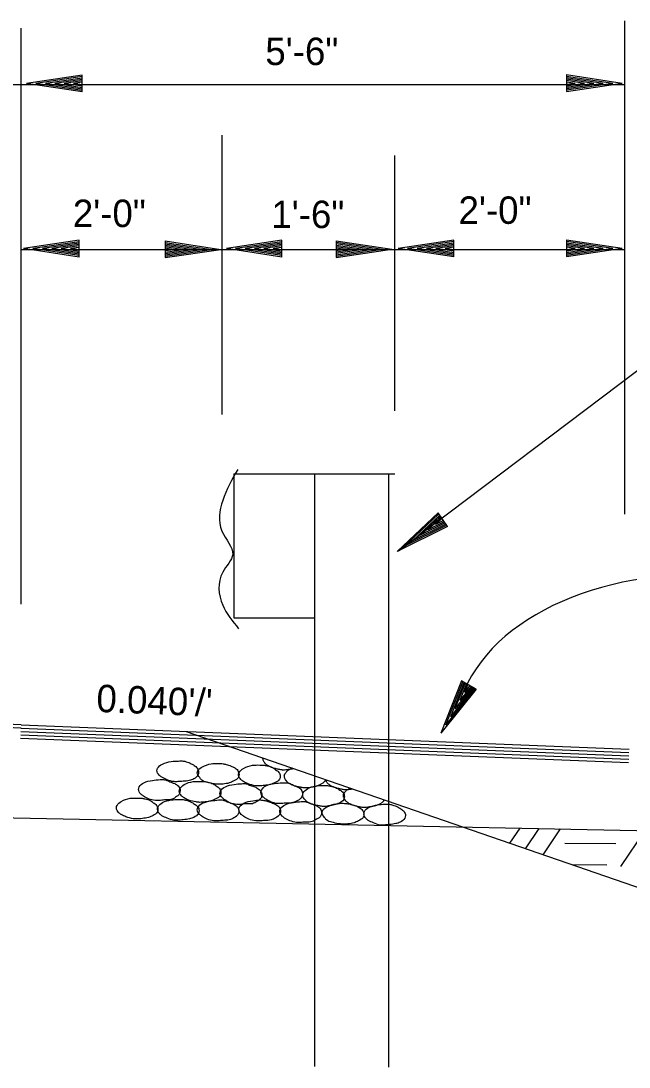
# Model space of a CAD drawing. Extents: x 1929624 to 1935547, y 596315 to 605721.
# Drawn here: x 1933028.1 to 1933162.8, y 604729.9 to 604961.5 of the extents above; entities that cross this region are included whole.
import ezdxf

# ---------------------------------------------------------------- set-up
doc = ezdxf.new("R2010")
doc.units = 0
doc.layers.add('Default', color=7, linetype='Continuous')
doc.layers.add('R_Border', color=7, linetype='Continuous')

msp = doc.modelspace()

# ---------------------------------------------------------------- linework, layer by layer
at = {"layer": 'Default'}
for p, q in [((1933161.84, 604852.3), (1933161.84, 604961.54)), ((1933028.14, 604832.41), (1933028.14, 604959.96)), ((1933148.9, 604949.65), (1933161.23, 604947.78)), ((1933148.9, 604949.65), (1933148.9, 604945.94)), ((1932831.31, 604947.46), (1933161.84, 604947.46)), ((1933041.68, 604949.53), (1933029.35, 604947.68)), ((1933041.68, 604945.81), (1933029.35, 604947.68)), ((1933041.68, 604949.21), (1933031.42, 604947.68)), ((1933041.68, 604946.13), (1933031.42, 604947.68)), ((1933041.68, 604948.89), (1933033.53, 604947.68)), ((1933041.68, 604946.45), (1933033.53, 604947.68)), ((1933041.68, 604948.59), (1933035.6, 604947.68)), ((1933041.68, 604946.75), (1933035.6, 604947.68)), ((1933041.68, 604948.27), (1933037.67, 604947.68)), ((1933041.68, 604947.07), (1933037.67, 604947.68)), ((1933041.68, 604947.95), (1933039.73, 604947.68)), ((1933041.68, 604947.39), (1933039.73, 604947.68)), ((1933041.68, 604945.81), (1933041.68, 604949.53)), ((1933148.9, 604949.33), (1933159.16, 604947.78)), ((1933148.9, 604949.01), (1933157.04, 604947.78)), ((1933148.9, 604948.72), (1933154.98, 604947.78)), ((1933148.9, 604948.4), (1933152.91, 604947.78)), ((1933148.9, 604948.08), (1933150.84, 604947.78)), ((1933148.9, 604945.94), (1933161.23, 604947.78)), ((1933148.9, 604947.19), (1933152.91, 604947.78)), ((1933148.9, 604946.58), (1933157.04, 604947.78)), ((1933148.9, 604946.26), (1933159.16, 604947.78)), ((1933148.9, 604946.87), (1933154.98, 604947.78)), ((1933148.9, 604947.51), (1933150.84, 604947.78)), ((1933072.7, 604874.4), (1933072.7, 604936.27)), ((1933110.91, 604875.2), (1933110.91, 604931.76)), ((1933041.01, 604912.97), (1933028.69, 604911.12)), ((1933041.01, 604912.65), (1933030.75, 604911.12)), ((1933041.01, 604909.25), (1933041.01, 604912.97)), ((1933060.03, 604912.84), (1933072.36, 604910.97)), ((1933060.03, 604912.84), (1933060.03, 604909.13)), ((1933060.03, 604912.52), (1933070.29, 604910.97)), ((1933085.91, 604912.97), (1933073.59, 604911.12)), ((1933085.91, 604912.65), (1933075.65, 604911.12)), ((1933085.91, 604909.25), (1933085.91, 604912.97)), ((1933097.9, 604912.87), (1933110.22, 604911)), ((1933097.9, 604912.87), (1933097.9, 604909.15)), ((1933097.9, 604912.55), (1933108.16, 604911)), ((1933124, 604912.99), (1933111.67, 604911.15)), ((1933124, 604912.67), (1933113.74, 604911.15)), ((1933124, 604909.28), (1933124, 604912.99)), ((1933148.9, 604913.07), (1933161.23, 604911.2)), ((1933148.9, 604913.07), (1933148.9, 604909.35)), ((1933148.9, 604912.75), (1933159.16, 604911.2)), ((1933028.14, 604910.9), (1933161.84, 604910.9)), ((1933041.01, 604909.25), (1933028.69, 604911.12)), ((1933041.01, 604909.57), (1933030.75, 604911.12)), ((1933041.01, 604912.33), (1933032.87, 604911.12)), ((1933041.01, 604909.89), (1933032.87, 604911.12)), ((1933041.01, 604912.03), (1933034.93, 604911.12)), ((1933041.01, 604910.19), (1933034.93, 604911.12)), ((1933041.01, 604911.71), (1933037, 604911.12)), ((1933041.01, 604910.51), (1933037, 604911.12)), ((1933041.01, 604911.39), (1933039.07, 604911.12)), ((1933041.01, 604910.83), (1933039.07, 604911.12)), ((1933060.03, 604912.2), (1933068.17, 604910.97)), ((1933060.03, 604911.91), (1933066.11, 604910.97)), ((1933060.03, 604911.59), (1933064.04, 604910.97)), ((1933060.03, 604911.27), (1933061.97, 604910.97)), ((1933060.03, 604909.13), (1933072.36, 604910.97)), ((1933060.03, 604910.38), (1933064.04, 604910.97)), ((1933060.03, 604909.77), (1933068.17, 604910.97)), ((1933060.03, 604909.45), (1933070.29, 604910.97)), ((1933060.03, 604910.06), (1933066.11, 604910.97)), ((1933060.03, 604910.7), (1933061.97, 604910.97)), ((1933085.91, 604909.25), (1933073.59, 604911.12)), ((1933085.91, 604909.57), (1933075.65, 604911.12)), ((1933085.91, 604912.33), (1933077.77, 604911.12)), ((1933085.91, 604909.89), (1933077.77, 604911.12)), ((1933085.91, 604912.03), (1933079.84, 604911.12)), ((1933085.91, 604910.19), (1933079.84, 604911.12)), ((1933085.91, 604911.71), (1933081.9, 604911.12)), ((1933085.91, 604910.51), (1933081.9, 604911.12)), ((1933085.91, 604911.39), (1933083.97, 604911.12)), ((1933085.91, 604910.83), (1933083.97, 604911.12)), ((1933097.9, 604912.23), (1933106.04, 604911)), ((1933097.9, 604911.93), (1933103.97, 604911)), ((1933097.9, 604911.61), (1933101.91, 604911)), ((1933097.9, 604911.29), (1933099.84, 604911)), ((1933097.9, 604909.15), (1933110.22, 604911)), ((1933097.9, 604910.41), (1933101.91, 604911)), ((1933097.9, 604909.79), (1933106.04, 604911)), ((1933097.9, 604909.47), (1933108.16, 604911)), ((1933097.9, 604910.09), (1933103.97, 604911)), ((1933097.9, 604910.73), (1933099.84, 604911)), ((1933124, 604909.28), (1933111.67, 604911.15)), ((1933124, 604909.6), (1933113.74, 604911.15)), ((1933124, 604912.35), (1933115.86, 604911.15)), ((1933124, 604909.92), (1933115.86, 604911.15)), ((1933124, 604912.06), (1933117.92, 604911.15)), ((1933124, 604910.21), (1933117.92, 604911.15)), ((1933124, 604911.74), (1933119.99, 604911.15)), ((1933124, 604910.53), (1933119.99, 604911.15)), ((1933124, 604911.42), (1933122.06, 604911.15)), ((1933124, 604910.85), (1933122.06, 604911.15)), ((1933148.9, 604912.43), (1933157.04, 604911.2)), ((1933148.9, 604912.13), (1933154.98, 604911.2)), ((1933148.9, 604911.81), (1933152.91, 604911.2)), ((1933148.9, 604911.49), (1933150.84, 604911.2)), ((1933148.9, 604909.35), (1933161.23, 604911.2)), ((1933148.9, 604910.61), (1933152.91, 604911.2)), ((1933148.9, 604909.99), (1933157.04, 604911.2)), ((1933148.9, 604909.67), (1933159.16, 604911.2)), ((1933148.9, 604910.29), (1933154.98, 604911.2)), ((1933148.9, 604910.92), (1933150.84, 604911.2)), ((1933111.72, 604844.22), (1933181.03, 604896.61)), ((1933075.26, 604861.23), (1933075.26, 604829.39)), ((1933075.26, 604861.23), (1933110.91, 604861.23)), ((1933093.1, 604861.23), (1933093.1, 604730.04)), ((1933109.48, 604861.08), (1933109.48, 604729.92)), ((1933120.47, 604852.64), (1933111.4, 604844.08)), ((1933120.66, 604852.4), (1933113.08, 604845.24)), ((1933122.56, 604849.64), (1933120.47, 604852.64)), ((1933120.86, 604852.11), (1933114.88, 604846.51)), ((1933122.19, 604850.14), (1933114.88, 604846.51)), ((1933120.98, 604851.85), (1933116.55, 604847.67)), ((1933122.02, 604850.4), (1933116.55, 604847.67)), ((1933121.17, 604851.64), (1933118.22, 604848.85)), ((1933121.82, 604850.67), (1933118.22, 604848.85)), ((1933121.34, 604851.37), (1933119.92, 604850.04)), ((1933121.7, 604850.95), (1933119.92, 604850.04)), ((1933122.56, 604849.64), (1933111.4, 604844.08)), ((1933122.41, 604849.87), (1933113.08, 604845.24)), ((1933075.26, 604829.39), (1933093.1, 604829.39)), ((1933125.7, 604815.46), (1933121.12, 604803.85)), ((1933125.94, 604815.27), (1933122.16, 604805.65)), ((1933128.9, 604813.59), (1933125.7, 604815.46)), ((1933128.9, 604813.59), (1933121.12, 604803.85)), ((1933128.65, 604813.76), (1933122.16, 604805.65)), ((1933126.24, 604815.12), (1933123.21, 604807.49)), ((1933128.33, 604813.89), (1933123.21, 604807.49)), ((1933126.49, 604814.97), (1933124.22, 604809.24)), ((1933128.08, 604814.06), (1933124.22, 604809.24)), ((1933126.78, 604814.82), (1933125.28, 604811.06)), ((1933127.81, 604814.21), (1933125.28, 604811.06)), ((1933127.08, 604814.65), (1933126.34, 604812.83)), ((1933127.54, 604814.38), (1933126.34, 604812.83)), ((1933028.14, 604805.69), (1932880.52, 604811.6)), ((1933028.14, 604804.96), (1932880.52, 604810.86)), ((1933028.08, 604804.22), (1933162.73, 604798.83)), ((1933028.1, 604804.96), (1933162.76, 604799.57)), ((1933028.14, 604805.69), (1933162.8, 604800.31)), ((1933064.67, 604804.23), (1933125.91, 604783.09)), ((1933028.02, 604802.74), (1933162.68, 604797.35)), ((1933028.05, 604803.48), (1933162.7, 604798.09)), ((1932826.87, 604789.04), (1933220.25, 604781.21)), ((1933125.91, 604783.09), (1933249.97, 604740.26))]:
    msp.add_line(p, q, dxfattribs=at)
msp.add_ellipse((1933185.01, 604798.43), major_axis=(-60.8, 7.42), ratio=0.655798, start_param=4.712389, end_param=6.093533, dxfattribs=at)
for points in [[(1933076.12, 604862.26), (1933072.78, 604855.35), (1933072.6, 604848.6), (1933075.01, 604843.41), (1933072.78, 604839.48), (1933072.78, 604832.22), (1933076.32, 604826.98)], [(1933063.01, 604797.68), (1933061.38, 604797.58), (1933059.42, 604796.99), (1933058.38, 604796.06), (1933058.23, 604795.52), (1933058.73, 604794.53), (1933059.32, 604794.09), (1933060.45, 604793.55), (1933062.02, 604793.11), (1933062.86, 604793.11), (1933064.04, 604793.2), (1933065.37, 604793.35), (1933066.4, 604793.75), (1933067.29, 604794.58), (1933067.44, 604795.22), (1933067.14, 604796.11), (1933066.5, 604796.7), (1933065.81, 604797.09), (1933064.73, 604797.53), (1933064.04, 604797.68), (1933063.01, 604797.68)], [(1933071.82, 604797.16), (1933070.2, 604797.06), (1933068.28, 604796.37), (1933067.3, 604795.58), (1933067.15, 604795.04), (1933067.69, 604794.01), (1933068.13, 604793.47), (1933069.31, 604792.97), (1933070.79, 604792.63), (1933071.63, 604792.53), (1933072.86, 604792.58), (1933074.24, 604792.83), (1933075.22, 604793.27), (1933076.25, 604794.06), (1933076.4, 604794.7), (1933076.11, 604795.58), (1933075.37, 604796.22), (1933074.63, 604796.57), (1933073.55, 604796.91), (1933072.86, 604797.06), (1933071.82, 604797.16)], [(1933081, 604796.79), (1933079.38, 604796.74), (1933077.41, 604796.05), (1933076.43, 604795.16), (1933076.28, 604794.57), (1933076.82, 604793.59), (1933077.36, 604793.15), (1933078.44, 604792.65), (1933080.02, 604792.21), (1933080.85, 604792.16), (1933082.03, 604792.26), (1933083.36, 604792.51), (1933084.4, 604792.9), (1933085.38, 604793.69), (1933085.53, 604794.28), (1933085.23, 604795.16), (1933084.5, 604795.75), (1933083.81, 604796.25), (1933082.72, 604796.59), (1933082.03, 604796.74), (1933081, 604796.79)], [(1933081.62, 604798.38), (1933081.62, 604798.35), (1933081.62, 604798.28), (1933081.63, 604798.21), (1933081.7, 604797.95), (1933081.82, 604797.68), (1933081.97, 604797.43), (1933082.07, 604797.3), (1933082.17, 604797.18), (1933082.42, 604796.93), (1933082.71, 604796.74), (1933082.97, 604796.59), (1933083.24, 604796.46), (1933083.51, 604796.35), (1933083.79, 604796.25), (1933084.57, 604796.03), (1933085.36, 604795.85), (1933085.78, 604795.78), (1933085.99, 604795.76), (1933086.2, 604795.75), (1933086.79, 604795.78), (1933087.09, 604795.81), (1933087.38, 604795.85), (1933087.9, 604795.93), (1933088.42, 604796.03)], [(1933088.28, 604796.08), (1933087.98, 604795.96), (1933087.74, 604795.85), (1933087.5, 604795.73), (1933087.21, 604795.55), (1933086.95, 604795.33), (1933086.73, 604795.08), (1933086.62, 604794.94), (1933086.51, 604794.79), (1933086.44, 604794.66), (1933086.39, 604794.52), (1933086.36, 604794.39), (1933086.36, 604794.32), (1933086.37, 604794.25), (1933086.44, 604793.98), (1933086.56, 604793.72), (1933086.71, 604793.47), (1933086.81, 604793.34), (1933086.91, 604793.22), (1933087.16, 604792.97), (1933087.45, 604792.78), (1933087.71, 604792.63), (1933087.98, 604792.5), (1933088.25, 604792.38), (1933088.53, 604792.28), (1933089.31, 604792.06), (1933090.11, 604791.89), (1933090.94, 604791.79), (1933091.09, 604791.79), (1933091.24, 604791.8), (1933091.53, 604791.82), (1933092.12, 604791.89), (1933092.46, 604791.94), (1933092.79, 604792), (1933093.12, 604792.06), (1933093.45, 604792.14), (1933093.72, 604792.21), (1933093.98, 604792.3), (1933094.23, 604792.41), (1933094.49, 604792.53), (1933094.76, 604792.68), (1933095.02, 604792.85), (1933095.25, 604793.05), (1933095.36, 604793.18), (1933095.47, 604793.32), (1933095.54, 604793.44), (1933095.59, 604793.56)], [(1933058.93, 604793.57), (1933057.21, 604793.38), (1933055.29, 604792.88), (1933054.31, 604791.95), (1933054.16, 604791.41), (1933054.65, 604790.37), (1933055.24, 604789.93), (1933056.32, 604789.34), (1933057.9, 604788.95), (1933058.69, 604788.95), (1933059.92, 604789.05), (1933061.29, 604789.14), (1933062.33, 604789.64), (1933063.21, 604790.47), (1933063.36, 604791.11), (1933063.07, 604792), (1933062.33, 604792.59), (1933061.64, 604792.88), (1933060.56, 604793.33), (1933059.92, 604793.52), (1933058.93, 604793.57)], [(1933067.86, 604793.15), (1933066.24, 604793.11), (1933064.27, 604792.47), (1933063.29, 604791.53), (1933063.14, 604790.99), (1933063.68, 604789.96), (1933064.22, 604789.51), (1933065.3, 604789.02), (1933066.88, 604788.63), (1933067.72, 604788.53), (1933068.9, 604788.63), (1933070.22, 604788.87), (1933071.26, 604789.27), (1933072.24, 604790.05), (1933072.39, 604790.69), (1933072.09, 604791.58), (1933071.36, 604792.17), (1933070.67, 604792.61), (1933069.59, 604792.96), (1933068.9, 604793.11), (1933067.86, 604793.15)], [(1933076.96, 604792.65), (1933075.33, 604792.51), (1933073.37, 604791.97), (1933072.33, 604791.03), (1933072.18, 604790.49), (1933072.73, 604789.51), (1933073.27, 604789.06), (1933074.4, 604788.42), (1933075.92, 604788.08), (1933076.76, 604788.08), (1933077.94, 604788.18), (1933079.37, 604788.23), (1933080.35, 604788.72), (1933081.29, 604789.55), (1933081.44, 604790.19), (1933081.14, 604791.08), (1933080.45, 604791.67), (1933079.71, 604792.01), (1933078.68, 604792.36), (1933077.99, 604792.65), (1933076.96, 604792.65)], [(1933085.91, 604792.88), (1933084.29, 604792.69), (1933082.37, 604792.2), (1933081.39, 604791.26), (1933081.24, 604790.72), (1933081.78, 604789.69), (1933082.32, 604789.24), (1933083.4, 604788.65), (1933084.98, 604788.26), (1933085.77, 604788.26), (1933087, 604788.36), (1933088.33, 604788.46), (1933089.41, 604788.95), (1933090.34, 604789.78), (1933090.49, 604790.42), (1933090.19, 604791.31), (1933089.46, 604791.9), (1933088.72, 604792.2), (1933087.69, 604792.69), (1933086.95, 604792.84), (1933085.91, 604792.88)], [(1933095.21, 604792.24), (1933093.59, 604792.2), (1933091.62, 604791.56), (1933090.64, 604790.62), (1933090.49, 604790.08), (1933091.03, 604789.05), (1933091.57, 604788.6), (1933092.66, 604788.11), (1933094.23, 604787.72), (1933095.07, 604787.62), (1933096.25, 604787.72), (1933097.58, 604787.96), (1933098.61, 604788.36), (1933099.59, 604789.14), (1933099.74, 604789.78), (1933099.45, 604790.67), (1933098.71, 604791.26), (1933098.02, 604791.7), (1933096.94, 604792.05), (1933096.25, 604792.2), (1933095.21, 604792.24)], [(1933095.54, 604793.58), (1933095.62, 604793.37), (1933095.73, 604793.17), (1933095.86, 604792.98), (1933096.01, 604792.79), (1933096.27, 604792.54), (1933096.55, 604792.35), (1933096.82, 604792.21), (1933097.08, 604792.07), (1933097.35, 604791.96), (1933097.63, 604791.86), (1933098.42, 604791.64), (1933099.21, 604791.46), (1933099.63, 604791.4), (1933099.84, 604791.37), (1933100.05, 604791.37), (1933100.64, 604791.39), (1933101.23, 604791.46), (1933101.53, 604791.51)], [(1933101.11, 604791.65), (1933100.85, 604791.53), (1933100.72, 604791.47), (1933100.59, 604791.4), (1933100.29, 604791.22), (1933100.04, 604791), (1933099.81, 604790.75), (1933099.71, 604790.61), (1933099.6, 604790.46), (1933099.52, 604790.33), (1933099.47, 604790.19), (1933099.45, 604790.06), (1933099.45, 604789.99), (1933099.45, 604789.92), (1933099.53, 604789.65), (1933099.64, 604789.39), (1933099.8, 604789.13), (1933099.89, 604789.01), (1933099.99, 604788.89), (1933100.25, 604788.64), (1933100.54, 604788.45), (1933100.8, 604788.3), (1933101.07, 604788.17), (1933101.34, 604788.05), (1933101.62, 604787.95), (1933102.4, 604787.73), (1933103.19, 604787.56), (1933104.03, 604787.46), (1933104.18, 604787.46), (1933104.32, 604787.47), (1933104.62, 604787.49), (1933105.21, 604787.56), (1933105.55, 604787.61), (1933105.88, 604787.67), (1933106.21, 604787.73), (1933106.54, 604787.81), (1933106.81, 604787.88), (1933107.06, 604787.97), (1933107.32, 604788.08), (1933107.57, 604788.2), (1933107.85, 604788.35), (1933108.11, 604788.52), (1933108.34, 604788.72), (1933108.45, 604788.85), (1933108.5, 604788.92), (1933108.56, 604788.99), (1933108.6, 604789.07)], [(1933053.91, 604789.48), (1933052.29, 604789.43), (1933050.32, 604788.74), (1933049.39, 604787.86), (1933049.24, 604787.27), (1933049.73, 604786.28), (1933050.32, 604785.84), (1933051.35, 604785.35), (1933052.98, 604784.9), (1933053.76, 604784.86), (1933055, 604784.95), (1933056.32, 604785.2), (1933057.36, 604785.59), (1933058.29, 604786.38), (1933058.44, 604786.97), (1933058.14, 604787.86), (1933057.41, 604788.45), (1933056.72, 604788.94), (1933055.63, 604789.28), (1933054.95, 604789.43), (1933053.91, 604789.48)], [(1933063.02, 604789.19), (1933061.39, 604789.05), (1933059.42, 604788.46), (1933058.49, 604787.57), (1933058.34, 604786.98), (1933058.83, 604786), (1933059.33, 604785.55), (1933060.46, 604785.06), (1933061.98, 604784.57), (1933062.82, 604784.57), (1933064.05, 604784.67), (1933065.43, 604784.86), (1933066.41, 604785.21), (1933067.4, 604786.09), (1933067.54, 604786.68), (1933067.25, 604787.57), (1933066.51, 604788.16), (1933065.77, 604788.6), (1933064.74, 604789), (1933064.05, 604789.14), (1933063.02, 604789.19)], [(1933071.87, 604789.06), (1933070.24, 604788.87), (1933068.27, 604788.32), (1933067.29, 604787.44), (1933067.14, 604786.85), (1933067.68, 604785.86), (1933068.22, 604785.42), (1933069.31, 604784.83), (1933070.83, 604784.44), (1933071.67, 604784.44), (1933072.9, 604784.54), (1933074.23, 604784.63), (1933075.26, 604785.08), (1933076.24, 604785.96), (1933076.39, 604786.55), (1933076.1, 604787.44), (1933075.36, 604788.03), (1933074.62, 604788.37), (1933073.54, 604788.77), (1933072.9, 604789.01), (1933071.87, 604789.06)], [(1933081.12, 604789.07), (1933079.45, 604788.87), (1933077.48, 604788.33), (1933076.5, 604787.45), (1933076.35, 604786.86), (1933076.89, 604785.87), (1933077.43, 604785.43), (1933078.57, 604784.79), (1933080.09, 604784.45), (1933080.88, 604784.45), (1933082.11, 604784.49), (1933083.49, 604784.64), (1933084.52, 604785.08), (1933085.45, 604785.97), (1933085.6, 604786.56), (1933085.31, 604787.45), (1933084.57, 604788.04), (1933083.83, 604788.38), (1933082.8, 604788.73), (1933082.16, 604788.92), (1933081.12, 604789.07)], [(1933090.19, 604788.7), (1933088.47, 604788.5), (1933086.6, 604788.01), (1933085.57, 604787.08), (1933085.42, 604786.54), (1933085.96, 604785.5), (1933086.5, 604785.06), (1933087.64, 604784.47), (1933089.16, 604784.08), (1933089.95, 604784.08), (1933091.18, 604784.17), (1933092.61, 604784.27), (1933093.59, 604784.77), (1933094.53, 604785.6), (1933094.67, 604786.24), (1933094.38, 604787.13), (1933093.64, 604787.72), (1933092.95, 604788.01), (1933091.87, 604788.41), (1933091.23, 604788.65), (1933090.19, 604788.7)], [(1933099.47, 604788.32), (1933097.85, 604788.23), (1933095.93, 604787.54), (1933094.94, 604786.75), (1933094.8, 604786.21), (1933095.34, 604785.18), (1933095.78, 604784.63), (1933096.96, 604784.14), (1933098.44, 604783.8), (1933099.27, 604783.7), (1933100.5, 604783.75), (1933101.88, 604783.99), (1933102.87, 604784.44), (1933103.9, 604785.22), (1933104.05, 604785.86), (1933103.75, 604786.75), (1933103.01, 604787.39), (1933102.28, 604787.73), (1933101.19, 604788.08), (1933100.5, 604788.23), (1933099.47, 604788.32)], [(1933108.72, 604788.14), (1933107.1, 604787.99), (1933105.13, 604787.4), (1933104.19, 604786.51), (1933104.05, 604785.92), (1933104.54, 604784.94), (1933105.03, 604784.49), (1933106.16, 604784), (1933107.69, 604783.51), (1933108.52, 604783.51), (1933109.75, 604783.61), (1933111.13, 604783.81), (1933112.12, 604784.15), (1933113.1, 604785.04), (1933113.25, 604785.63), (1933112.95, 604786.51), (1933112.22, 604787.1), (1933111.48, 604787.55), (1933110.44, 604787.94), (1933109.75, 604788.09), (1933108.72, 604788.14)]]:
    msp.add_spline(points, degree=3, dxfattribs=at)
at = {"layer": 'R_Border'}
for p, q in [((1933136.37, 604779.48), (1933138.64, 604782.84)), ((1933139.86, 604778.27), (1933142.88, 604782.75)), ((1933143.72, 604776.94), (1933147.58, 604782.66)), ((1933160.95, 604774.3), (1933166.34, 604782.29)), ((1933148.53, 604779.5), (1933159.84, 604779.4)), ((1933150.11, 604774.74), (1933157.89, 604774.67))]:
    msp.add_line(p, q, dxfattribs=at)

# ---------------------------------------------------------------- texts
at = {"layer": 'Default'}
for s, rotation, p in [('5\'-6"', 360, (1933082.22, 604951.77)), ('2\'-0"', 360, (1933039.59, 604915.9)), ('1\'-6"', 360, (1933083.55, 604915.68)), ('2\'-0"', 360, (1933125.01, 604916.61)), ("0.040'/'", 357.7094, (1933044.72, 604808.56))]:
    msp.add_text(s, height=6.075, rotation=rotation, dxfattribs=at).set_placement(p)

doc.saveas('drawing.dxf')
